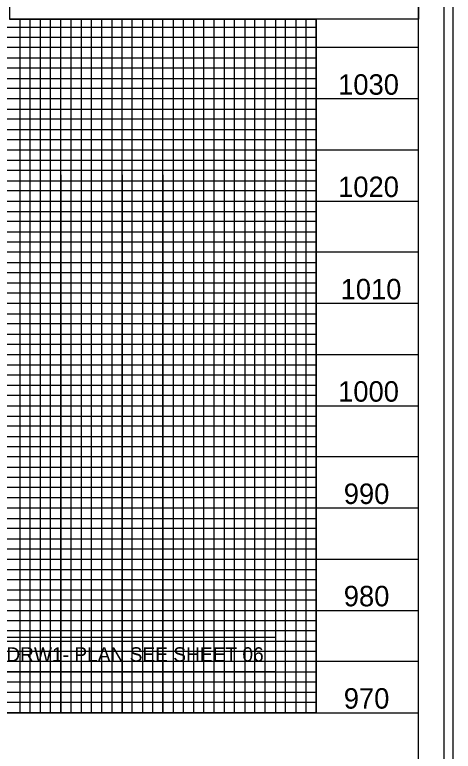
# Model space of a CAD drawing. Extents: x 1260439 to 1262228, y 742196 to 743296.
# Drawn here: x 1261908.3 to 1262122.8, y 742751.9 to 743111.8 of the extents above; entities that cross this region are included whole.
import ezdxf

# ---------------------------------------------------------------- set-up
doc = ezdxf.new("R2010")
doc.units = 0
for name, color, linetype in [('Exist Vertical Profile Vertical Axis Label', 7, 'Continuous'), ('Prop Grid Mask', 7, 'Continuous'), ('Prop PFL Text', 7, 'Continuous'), ('Scratch_Level_0', 7, 'Continuous'), ('Sheet Layout Profile Border Port 1', 7, 'Continuous'), ('Sheet Plot Border Inside CELL', 7, 'Continuous'), ('Sheet Plot Border Outside CELL', 7, 'Continuous'), ('Sheet Profile CELL', 7, 'Continuous'), ('Sheet Profile Grid Major CELL', 7, 'Continuous'), ('Sheet Profile Grid Middle CELL', 7, 'Continuous'), ('Sheet Profile Grid Minor CELL', 7, 'Continuous'), ('Sheet Sticker Exception Certification CELL', 7, 'Continuous')]:
    doc.layers.add(name, color=color, linetype=linetype)

msp = doc.modelspace()

# ---------------------------------------------------------------- linework, layer by layer
at = {"layer": 'Prop Grid Mask'}
msp.add_lwpolyline([(1261875.75, 742807.74), (1262035.75, 742807.74), (1262035.75, 742790.74), (1261875.75, 742790.74)], close=True, dxfattribs=at)
at = {"layer": 'Scratch_Level_0'}
msp.add_lwpolyline([(1261405.75, 743270.74), (1261805.75, 743270.74), (1261805.75, 743220.74), (1261905.75, 743220.74), (1261905.7, 743109.69), (1262055.75, 743109.69), (1262055.75, 742770.74), (1261405.75, 742770.74)], close=True, dxfattribs=at)
at = {"layer": 'Sheet Layout Profile Border Port 1'}
msp.add_lwpolyline([(1260655.75, 743109.69), (1260655.75, 742770.74), (1262055.75, 742770.74), (1262055.75, 743109.69)], dxfattribs=at)
msp.add_lwpolyline([(1260655.75, 743109.69), (1260655.75, 742770.74), (1262055.75, 742770.74), (1262055.75, 743109.69)], dxfattribs=at)
msp.add_lwpolyline([(1260655.75, 743109.69), (1260655.75, 742770.74), (1262055.75, 742770.74), (1262055.75, 743109.69)], dxfattribs=at)
at = {"layer": 'Sheet Plot Border Inside CELL'}
msp.add_lwpolyline([(1260451.75, 742218.19), (1262118.25, 742218.19), (1262118.25, 743273.29), (1260451.75, 743273.29)], close=True, dxfattribs=at)
at = {"layer": 'Sheet Plot Border Outside CELL'}
msp.add_lwpolyline([(1260438.75, 742195.74), (1262122.75, 742195.74), (1262122.75, 743295.74), (1260438.75, 743295.74)], close=True, dxfattribs=at)
at = {"layer": 'Sheet Profile CELL'}
msp.add_line((1260605.75, 742770.74), (1262105.75, 742770.74), dxfattribs=at)
msp.add_lwpolyline([(1262105.75, 743270.74), (1260605.75, 743270.74), (1260605.75, 742220.74), (1262105.75, 742220.74)], close=True, dxfattribs=at)
at = {"layer": 'Sheet Profile Grid Major CELL'}
for points in [[(1262055.75, 743109.69), (1262055.75, 742770.74), (1262105.75, 742770.74), (1262105.75, 743120.74)], [(1261955.75, 743109.69), (1261955.75, 742770.74), (1262005.75, 742770.74), (1262005.75, 742770.74), (1262005.75, 743109.69)], [(1262105.75, 743070.74), (1261355.75, 743070.74)], [(1261355.75, 743020.74), (1262105.75, 743020.74)], [(1262105.75, 742970.74), (1261355.75, 742970.74)], [(1261355.75, 742920.74), (1262105.75, 742920.74)], [(1262105.75, 742870.74), (1261355.75, 742870.74)], [(1261355.75, 742820.74), (1262105.75, 742820.74)]]:
    msp.add_lwpolyline(points, dxfattribs=at)
at = {"layer": 'Sheet Profile Grid Middle CELL'}
for p, q in [((1261930.75, 742770.74), (1261930.75, 743109.69)), ((1261880.75, 742770.74), (1261930.75, 742770.74))]:
    msp.add_line(p, q, dxfattribs=at)
for points in [[(1261930.75, 743033.54), (1261930.75, 742770.74), (1261980.75, 742770.74), (1261980.75, 743109.69)], [(1261980.75, 743033.54), (1261980.75, 742770.74), (1262030.75, 742770.74), (1262030.75, 743109.69)], [(1262105.75, 743095.74), (1261355.75, 743095.74)], [(1261355.75, 743045.74), (1261930.75, 743045.74)], [(1261930.75, 743045.74), (1262105.75, 743045.74)], [(1262105.75, 742995.74), (1261355.75, 742995.74)], [(1261355.75, 742945.74), (1262105.75, 742945.74)], [(1262105.75, 742895.74), (1261355.75, 742895.74)], [(1261355.75, 742845.74), (1262105.75, 742845.74)], [(1262105.75, 742795.74), (1261355.75, 742795.74)]]:
    msp.add_lwpolyline(points, dxfattribs=at)
at = {"layer": 'Sheet Profile Grid Minor CELL'}
for p, q in [((1261405.75, 743105.74), (1262055.75, 743105.74)), ((1262055.75, 743085.74), (1261405.75, 743085.74)), ((1261405.75, 743080.74), (1262055.75, 743080.74)), ((1262055.75, 743060.74), (1261405.75, 743060.74)), ((1261405.75, 743055.74), (1262055.75, 743055.74)), ((1262055.75, 743035.74), (1261405.75, 743035.74)), ((1261405.75, 743030.74), (1262055.75, 743030.74)), ((1262055.75, 743025.74), (1261405.75, 743025.74)), ((1261405.75, 743015.74), (1262055.75, 743015.74)), ((1262055.75, 743010.74), (1261405.75, 743010.74)), ((1261405.75, 743005.74), (1262055.75, 743005.74)), ((1262055.75, 743000.74), (1261405.75, 743000.74)), ((1261405.75, 742990.74), (1262055.75, 742990.74)), ((1262055.75, 742985.74), (1261405.75, 742985.74)), ((1261405.75, 742980.74), (1262055.75, 742980.74)), ((1262055.75, 742975.74), (1261405.75, 742975.74)), ((1261405.75, 742965.74), (1262055.75, 742965.74)), ((1262055.75, 742960.74), (1261405.75, 742960.74)), ((1261405.75, 742955.74), (1262055.75, 742955.74)), ((1262055.75, 742950.74), (1261405.75, 742950.74)), ((1261405.75, 742940.74), (1262055.75, 742940.74)), ((1262055.75, 742935.74), (1261405.75, 742935.74)), ((1261405.75, 742930.74), (1262055.75, 742930.74)), ((1262055.75, 742925.74), (1261405.75, 742925.74)), ((1261405.75, 742915.74), (1262055.75, 742915.74)), ((1262055.75, 742910.74), (1261405.75, 742910.74)), ((1261405.75, 742905.74), (1262055.75, 742905.74)), ((1262055.75, 742900.74), (1261405.75, 742900.74)), ((1261405.75, 742890.74), (1262055.75, 742890.74)), ((1262055.75, 742885.74), (1261405.75, 742885.74)), ((1262055.75, 742880.74), (1261405.75, 742880.74)), ((1262055.75, 742875.74), (1261405.75, 742875.74)), ((1261405.75, 742865.74), (1262055.75, 742865.74)), ((1262055.75, 742860.74), (1261405.75, 742860.74)), ((1261405.75, 742855.74), (1262055.75, 742855.74)), ((1262055.75, 742850.74), (1261405.75, 742850.74)), ((1261405.75, 742840.74), (1262055.75, 742840.74)), ((1262055.75, 742835.74), (1261405.75, 742835.74)), ((1261405.75, 742830.74), (1262055.75, 742830.74)), ((1262055.75, 742825.74), (1261405.75, 742825.74)), ((1261405.75, 742815.74), (1262055.75, 742815.74)), ((1262055.75, 742810.74), (1261405.75, 742810.74)), ((1261405.75, 742805.74), (1262055.75, 742805.74)), ((1262055.75, 742800.74), (1261405.75, 742800.74)), ((1261405.75, 742790.74), (1262055.75, 742790.74)), ((1262055.75, 742785.74), (1261405.75, 742785.74)), ((1261405.75, 742780.74), (1262055.75, 742780.74))]:
    msp.add_line(p, q, dxfattribs=at)
for points in [[(1261910.75, 743109.69), (1261910.75, 742770.74), (1261915.75, 742770.74), (1261915.75, 743109.69)], [(1261920.75, 743109.69), (1261920.75, 742770.74), (1261925.75, 742770.74), (1261925.75, 743109.69)], [(1261935.75, 743109.69), (1261935.75, 742770.74), (1261935.75, 742770.74), (1261940.75, 742770.74), (1261945.75, 742770.74), (1261945.75, 743109.69)], [(1261940.75, 743109.69), (1261940.75, 742770.74)], [(1261950.75, 743109.69), (1261950.65, 742770.79), (1261955.65, 742770.79), (1261960.75, 742770.74), (1261960.75, 743109.69)], [(1261960.75, 743033.54), (1261960.75, 742770.74), (1261965.75, 742770.74), (1261965.75, 743109.69)], [(1261970.75, 743109.69), (1261970.75, 742770.74), (1261975.75, 742770.74), (1261975.75, 743109.69)], [(1261985.75, 743109.69), (1261985.75, 742770.74), (1261990.75, 742770.74), (1261990.75, 743109.69)], [(1261995.75, 743109.69), (1261995.75, 742770.74), (1262000.75, 742770.74), (1262000.75, 743109.69)], [(1262010.75, 743109.69), (1262010.75, 742770.74), (1262015.75, 742770.74), (1262015.75, 743109.69)], [(1262020.75, 743109.69), (1262020.75, 742770.74), (1262025.75, 742770.74), (1262025.75, 743109.69)], [(1262035.75, 743109.69), (1262035.75, 742770.74), (1262040.75, 742770.74), (1262040.75, 743109.69)], [(1262045.75, 743109.69), (1262045.75, 742770.74), (1262050.75, 742770.74), (1262050.75, 743109.69)], [(1262055.75, 743100.74), (1261405.75, 743100.74)], [(1261405.75, 743090.74), (1262055.75, 743090.74)], [(1262055.75, 743075.74), (1261405.75, 743075.74)], [(1261405.75, 743065.74), (1262055.75, 743065.74)], [(1262055.75, 743050.74), (1261405.75, 743050.74)], [(1261405.75, 743040.74), (1262055.75, 743040.74)], [(1262055.75, 742775.74), (1261405.75, 742775.74)]]:
    msp.add_lwpolyline(points, dxfattribs=at)
at = {"layer": 'Sheet Sticker Exception Certification CELL'}
for p, q in [((1262105.74, 743133.17), (1262105.74, 743109.67)), ((1262105.74, 743109.69), (1261905.7, 743109.69))]:
    msp.add_line(p, q, dxfattribs=at)

# ---------------------------------------------------------------- texts
at = {"layer": 'Exist Vertical Profile Vertical Axis Label'}
for s, p in [('1030', (1262066.43, 743072.74)), ('1020', (1262066.43, 743022.74)), ('1010', (1262067.63, 742972.74)), ('1000', (1262066.43, 742922.74)), ('990', (1262069.19, 742872.74)), ('980', (1262069.19, 742822.74)), ('970', (1262069.19, 742772.74))]:
    msp.add_text(s, height=10, dxfattribs=at).set_placement(p)
at = {"layer": 'Prop PFL Text'}
msp.add_text('FOR -DRW1- PLAN SEE SHEET 06', height=7, dxfattribs=at).set_placement((1261878.66, 742795.74))

doc.saveas('drawing.dxf')
